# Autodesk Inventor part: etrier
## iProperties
Author: Administrateur
Shininess: 60.0
PropertySet Name: _Private Model Information
Length Units: 11269
Angle Units: 11283
Time Units: 11279
Mass Units: 11290
Length Display Precision: 3
Angle Display Precision: 2
Compacted: False
Created: 2001-04
Part Number: etrier
Material: Par défaut
Document SubType Name: Modélisation
Designer: Administrateur
Control State: 0
Master: False
Checked Out: False
PropertySet Name: Design Tracking Control
Density: 0.0
Volumn: 0.0
Area: 0.0
PropertySet Name: Model Information
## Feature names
1. Hélicoïde2
2. Symétrie2 [Mirror]
